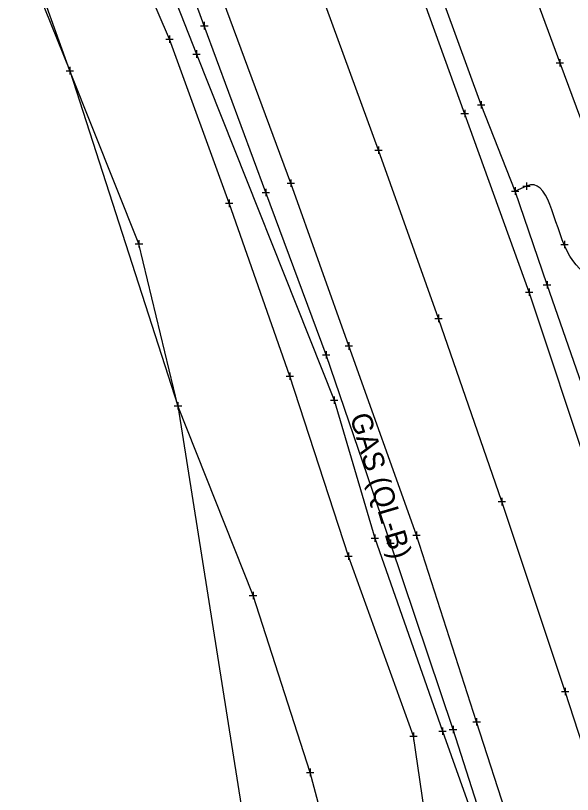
# Model space of a CAD drawing. Extents: x 2324380 to 2325559, y 691096 to 693386.
# Drawn here: x 2324992.8 to 2325067.6, y 692170 to 692274.6 of the extents above; entities that cross this region are included whole.
import ezdxf

# ---------------------------------------------------------------- set-up
doc = ezdxf.new("R2010")
doc.units = 0
for name, color, linetype in [('PM_X_CL_Double_Solid', 7, 'Continuous'), ('PM_X_Transverse_Line', 7, 'Continuous'), ('PV_X_COP', 7, 'Continuous'), ('PV_X_Driveway', 7, 'Continuous'), ('PV_X_EOP', 7, 'Continuous'), ('SV_X_Shot_Marker', 7, 'Continuous'), ('SV_X_Terrain_Boundary', 7, 'Continuous'), ('SV_X_Toe_of_Slope', 7, 'Continuous'), ('SV_X_Top_of_Bank', 7, 'Continuous'), ('UT_X_Gas', 7, 'Continuous'), ('UT_X_Gas_Text', 7, 'Continuous'), ('UT_X_Water', 7, 'Continuous')]:
    doc.layers.add(name, color=color, linetype=linetype)

msp = doc.modelspace()

# ---------------------------------------------------------------- linework, layer by layer
at = {"layer": 'PM_X_CL_Double_Solid'}
msp.add_lwpolyline([(2325089.48, 692110.68), (2325084.32, 692128.51), (2325075.39, 692156.76), (2325066.63, 692183.78), (2325058.11, 692209.28), (2325049.62, 692233.9), (2325041.55, 692256.48), (2325033.1, 692279.67), (2325023.32, 692305.87), (2325013.77, 692329.93)], dxfattribs=at)
at = {"layer": 'PM_X_Transverse_Line'}
for points in [[(2325119.99, 692049.57), (2325112.24, 692077.64), (2325103.35, 692107.53), (2325096.49, 692131.33), (2325087.35, 692159.17), (2325078.82, 692186.21), (2325070.07, 692212.52), (2325061.8, 692237.43), (2325045.09, 692283.67), (2325035.69, 692308.59), (2325025.65, 692334.45)], [(2325067.54, 692138.56), (2325063.39, 692152.82), (2325054.73, 692179.69), (2325046.66, 692204.76), (2325037.56, 692230.19), (2325029.78, 692252.06), (2325021.19, 692275.25), (2325011.82, 692300.8), (2325001.5, 692326.71)]]:
    msp.add_lwpolyline(points, dxfattribs=at)
at = {"layer": 'PV_X_COP'}
msp.add_lwpolyline([(2325108.45, 692046.03), (2325099.34, 692075.66), (2325091, 692105.35), (2325084.32, 692128.51), (2325075.39, 692156.76), (2325066.63, 692183.78), (2325058.11, 692209.28), (2325049.62, 692233.9), (2325041.55, 692256.48), (2325033.1, 692279.67), (2325023.32, 692305.87), (2325013.77, 692329.93)], dxfattribs=at)
at = {"layer": 'PV_X_Driveway'}
msp.add_line((2325061.43, 692251.66), (2325059.92, 692251), dxfattribs=at)
msp.add_open_spline([(2325090.6, 692235.9), (2325088.84, 692235.48), (2325083.93, 692235.28), (2325075.21, 692236.84), (2325065.59, 692240.39), (2325064.41, 692252.96), (2325061.43, 692251.66)], degree=3, dxfattribs=at)
at = {"layer": 'PV_X_EOP'}
for p, q in [((2325018.15, 692273.21), (2325008.31, 692299.88)), ((2325026.41, 692250.8), (2325018.15, 692273.21)), ((2325034.52, 692228.99), (2325026.41, 692250.8)), ((2325043.17, 692203.7), (2325034.52, 692228.99)), ((2325051.56, 692178.68), (2325043.17, 692203.7)), ((2325060.05, 692152.41), (2325051.56, 692178.68))]:
    msp.add_line(p, q, dxfattribs=at)
msp.add_lwpolyline([(2325123.25, 692051.46), (2325115.82, 692078.51), (2325110.86, 692095.71), (2325106.46, 692109.57), (2325099.73, 692132.13), (2325090.5, 692160.58), (2325082.22, 692186.84), (2325072.77, 692213.83), (2325064.19, 692238.4), (2325059.92, 692251), (2325055.34, 692262.57), (2325047.32, 692284.59), (2325037.78, 692309.71), (2325028.4, 692335.51)], dxfattribs=at)
at = {"layer": 'SV_X_Shot_Marker'}
for p, q in [((2325017.65, 692273.21), (2325018.65, 692273.21)), ((2325018.15, 692273.71), (2325018.15, 692272.71)), ((2325018.15, 692273.21), (2325018.15, 692273.21)), ((2325012.96, 692271.39), (2325013.96, 692271.39)), ((2325013.46, 692271.89), (2325013.46, 692270.89)), ((2325013.46, 692271.39), (2325013.46, 692271.39)), ((2325016.59, 692269.4), (2325017.59, 692269.4)), ((2325017.09, 692269.9), (2325017.09, 692268.9)), ((2325017.09, 692269.4), (2325017.09, 692269.4)), ((2325065.42, 692268.22), (2325066.42, 692268.22)), ((2325065.92, 692268.72), (2325065.92, 692267.72)), ((2325065.92, 692268.22), (2325065.92, 692268.22)), ((2324999.58, 692267.16), (2325000.58, 692267.16)), ((2325000.08, 692267.66), (2325000.08, 692266.66)), ((2325000.08, 692267.16), (2325000.08, 692267.16)), ((2325055.34, 692263.07), (2325055.34, 692262.07)), ((2325053.13, 692261.91), (2325053.13, 692260.91)), ((2325054.84, 692262.57), (2325055.84, 692262.57)), ((2325055.34, 692262.57), (2325055.34, 692262.57)), ((2325052.63, 692261.41), (2325053.63, 692261.41)), ((2325053.13, 692261.41), (2325053.13, 692261.41)), ((2325041.05, 692256.48), (2325042.05, 692256.48)), ((2325041.05, 692256.48), (2325042.05, 692256.48)), ((2325041.55, 692256.98), (2325041.55, 692255.98)), ((2325041.55, 692256.98), (2325041.55, 692255.98)), ((2325041.55, 692256.48), (2325041.55, 692256.48)), ((2325041.55, 692256.48), (2325041.55, 692256.48)), ((2325029.78, 692252.56), (2325029.78, 692251.56)), ((2325026.41, 692251.3), (2325026.41, 692250.3)), ((2325029.28, 692252.06), (2325030.28, 692252.06)), ((2325029.78, 692252.06), (2325029.78, 692252.06)), ((2325059.92, 692251.5), (2325059.92, 692250.5)), ((2325059.92, 692251.5), (2325059.92, 692250.5)), ((2325060.93, 692251.66), (2325061.93, 692251.66)), ((2325061.43, 692252.16), (2325061.43, 692251.16)), ((2325061.43, 692251.66), (2325061.43, 692251.66)), ((2325025.91, 692250.8), (2325026.91, 692250.8)), ((2325026.41, 692250.8), (2325026.41, 692250.8)), ((2325059.42, 692251), (2325060.42, 692251)), ((2325059.42, 692251), (2325060.42, 692251)), ((2325059.92, 692251), (2325059.92, 692251)), ((2325059.92, 692251), (2325059.92, 692251)), ((2325020.98, 692249.35), (2325021.98, 692249.35)), ((2325021.48, 692249.85), (2325021.48, 692248.85)), ((2325021.48, 692249.35), (2325021.48, 692249.35)), ((2325008.87, 692243.9), (2325009.87, 692243.9)), ((2325009.37, 692244.4), (2325009.37, 692243.4)), ((2325009.37, 692243.9), (2325009.37, 692243.9)), ((2325066.53, 692244.32), (2325066.53, 692243.32)), ((2325066.03, 692243.82), (2325067.03, 692243.82)), ((2325066.53, 692243.82), (2325066.53, 692243.82)), ((2325064.19, 692238.9), (2325064.19, 692237.9)), ((2325061.8, 692237.93), (2325061.8, 692236.93)), ((2325063.69, 692238.4), (2325064.69, 692238.4)), ((2325064.19, 692238.4), (2325064.19, 692238.4)), ((2325061.3, 692237.43), (2325062.3, 692237.43)), ((2325061.8, 692237.43), (2325061.8, 692237.43)), ((2325049.12, 692233.9), (2325050.12, 692233.9)), ((2325049.12, 692233.9), (2325050.12, 692233.9)), ((2325049.62, 692234.4), (2325049.62, 692233.4)), ((2325049.62, 692234.4), (2325049.62, 692233.4)), ((2325049.62, 692233.9), (2325049.62, 692233.9)), ((2325049.62, 692233.9), (2325049.62, 692233.9)), ((2325037.56, 692230.69), (2325037.56, 692229.69)), ((2325034.52, 692229.49), (2325034.52, 692228.49)), ((2325037.06, 692230.19), (2325038.06, 692230.19)), ((2325037.56, 692230.19), (2325037.56, 692230.19)), ((2325034.02, 692228.99), (2325035.02, 692228.99)), ((2325034.52, 692228.99), (2325034.52, 692228.99)), ((2325029.15, 692226.14), (2325030.15, 692226.14)), ((2325029.65, 692226.64), (2325029.65, 692225.64)), ((2325029.65, 692226.14), (2325029.65, 692226.14)), ((2325035.58, 692223.4), (2325035.58, 692222.4)), ((2325014.11, 692222.14), (2325015.11, 692222.14)), ((2325014.61, 692222.64), (2325014.61, 692221.64)), ((2325014.61, 692222.14), (2325014.61, 692222.14)), ((2325035.08, 692222.9), (2325036.08, 692222.9)), ((2325035.58, 692222.9), (2325035.58, 692222.9)), ((2325058.11, 692209.78), (2325058.11, 692208.78)), ((2325058.11, 692209.78), (2325058.11, 692208.78)), ((2325057.61, 692209.28), (2325058.61, 692209.28)), ((2325057.61, 692209.28), (2325058.61, 692209.28)), ((2325058.11, 692209.28), (2325058.11, 692209.28)), ((2325058.11, 692209.28), (2325058.11, 692209.28)), ((2325046.66, 692205.26), (2325046.66, 692204.26)), ((2325040.56, 692204.36), (2325041.56, 692204.36)), ((2325041.06, 692204.86), (2325041.06, 692203.86)), ((2325041.06, 692204.36), (2325041.06, 692204.36)), ((2325043.17, 692204.2), (2325043.17, 692203.2)), ((2325046.16, 692204.76), (2325047.16, 692204.76)), ((2325046.66, 692204.76), (2325046.66, 692204.76)), ((2325042.67, 692203.7), (2325043.67, 692203.7)), ((2325043.17, 692203.7), (2325043.17, 692203.7)), ((2325037.53, 692202.46), (2325037.53, 692201.46)), ((2325037.03, 692201.96), (2325038.03, 692201.96)), ((2325037.53, 692201.96), (2325037.53, 692201.96)), ((2325024.69, 692197.16), (2325024.69, 692196.16)), ((2325024.19, 692196.66), (2325025.19, 692196.66)), ((2325024.69, 692196.66), (2325024.69, 692196.66)), ((2325066.63, 692184.28), (2325066.63, 692183.28)), ((2325066.63, 692184.28), (2325066.63, 692183.28)), ((2325066.13, 692183.78), (2325067.13, 692183.78)), ((2325066.13, 692183.78), (2325067.13, 692183.78)), ((2325066.63, 692183.78), (2325066.63, 692183.78)), ((2325066.63, 692183.78), (2325066.63, 692183.78)), ((2325054.73, 692180.19), (2325054.73, 692179.19)), ((2325051.56, 692179.18), (2325051.56, 692178.18)), ((2325054.23, 692179.69), (2325055.23, 692179.69)), ((2325054.73, 692179.69), (2325054.73, 692179.69)), ((2325046.25, 692178.26), (2325046.25, 692177.26)), ((2325049.64, 692178.45), (2325050.64, 692178.45)), ((2325050.14, 692178.95), (2325050.14, 692177.95)), ((2325050.14, 692178.45), (2325050.14, 692178.45)), ((2325051.06, 692178.68), (2325052.06, 692178.68)), ((2325051.56, 692178.68), (2325051.56, 692178.68)), ((2325045.75, 692177.76), (2325046.75, 692177.76)), ((2325046.25, 692177.76), (2325046.25, 692177.76)), ((2325031.88, 692172.92), (2325032.88, 692172.92)), ((2325032.38, 692173.42), (2325032.38, 692172.42)), ((2325032.38, 692172.92), (2325032.38, 692172.92))]:
    msp.add_line(p, q, dxfattribs=at)
at = {"layer": 'SV_X_Terrain_Boundary'}
msp.add_lwpolyline([(2325110.91, 692166.99), (2325109.19, 692174.04), (2325100.28, 692217.91), (2325098.88, 692222), (2325093.57, 692236.62), (2325076.53, 692278.08), (2325068.46, 692300.04), (2325060.86, 692317.44), (2325050.46, 692344.77), (2325046.07, 692343.18), (2325028.4, 692335.51), (2325013.77, 692329.93), (2324997.75, 692325.76), (2324994.77, 692324.28), (2324978.96, 692319.34), (2325000.08, 692267.16), (2325014.61, 692222.14), (2325030.56, 692121.28)], dxfattribs=at)
at = {"layer": 'SV_X_Toe_of_Slope'}
msp.add_lwpolyline([(2325030.56, 692121.28), (2325044.25, 692124.98), (2325039.46, 692146.35), (2325032.38, 692172.92), (2325024.69, 692196.66), (2325014.61, 692222.14), (2325009.37, 692243.9), (2325000.08, 692267.16), (2324990.82, 692292.96), (2324978.96, 692319.34)], dxfattribs=at)
at = {"layer": 'SV_X_Top_of_Bank'}
msp.add_lwpolyline([(2325035.08, 692109.4), (2325044.3, 692119.16), (2325050, 692123.78), (2325050.31, 692149.89), (2325046.25, 692177.76), (2325037.53, 692201.96), (2325029.65, 692226.14), (2325021.48, 692249.35), (2325013.46, 692271.39), (2325002.03, 692298.08), (2324994.77, 692324.28)], dxfattribs=at)
at = {"layer": 'UT_X_Gas'}
msp.add_lwpolyline([(2324898.38, 692544.09), (2324919.05, 692496.67), (2324937.7, 692455), (2324959.41, 692406.62), (2324976.91, 692366.17), (2325000.38, 692311.88), (2325017.09, 692269.4), (2325035.58, 692222.9), (2325041.06, 692204.36), (2325050.14, 692178.45), (2325064.12, 692139.21), (2325054.72, 692138.03), (2325055.52, 692128.26), (2325054.24, 692120.72), (2325042.69, 692106.28), (2325010.21, 692097.08)], dxfattribs=at)
at = {"layer": 'UT_X_Water'}
msp.add_lwpolyline([(2324934.92, 692571.2), (2324956.29, 692529.58), (2324976.21, 692488), (2324991.94, 692453.33), (2325012.4, 692405.82), (2325031.94, 692356.27), (2325051.28, 692307.99), (2325065.92, 692268.22), (2325079.64, 692231.2), (2325091.06, 692197.41), (2325105.98, 692152.66), (2325121.62, 692099.73), (2325124.52, 692091.67), (2325134.64, 692057.74)], dxfattribs=at)

# ---------------------------------------------------------------- texts
at = {"layer": 'UT_X_Gas_Text'}
msp.add_text('GAS (QL-B)', height=2.8, rotation=286.4563, dxfattribs=at).set_placement((2325037.68, 692220.73))

doc.saveas('drawing.dxf')
